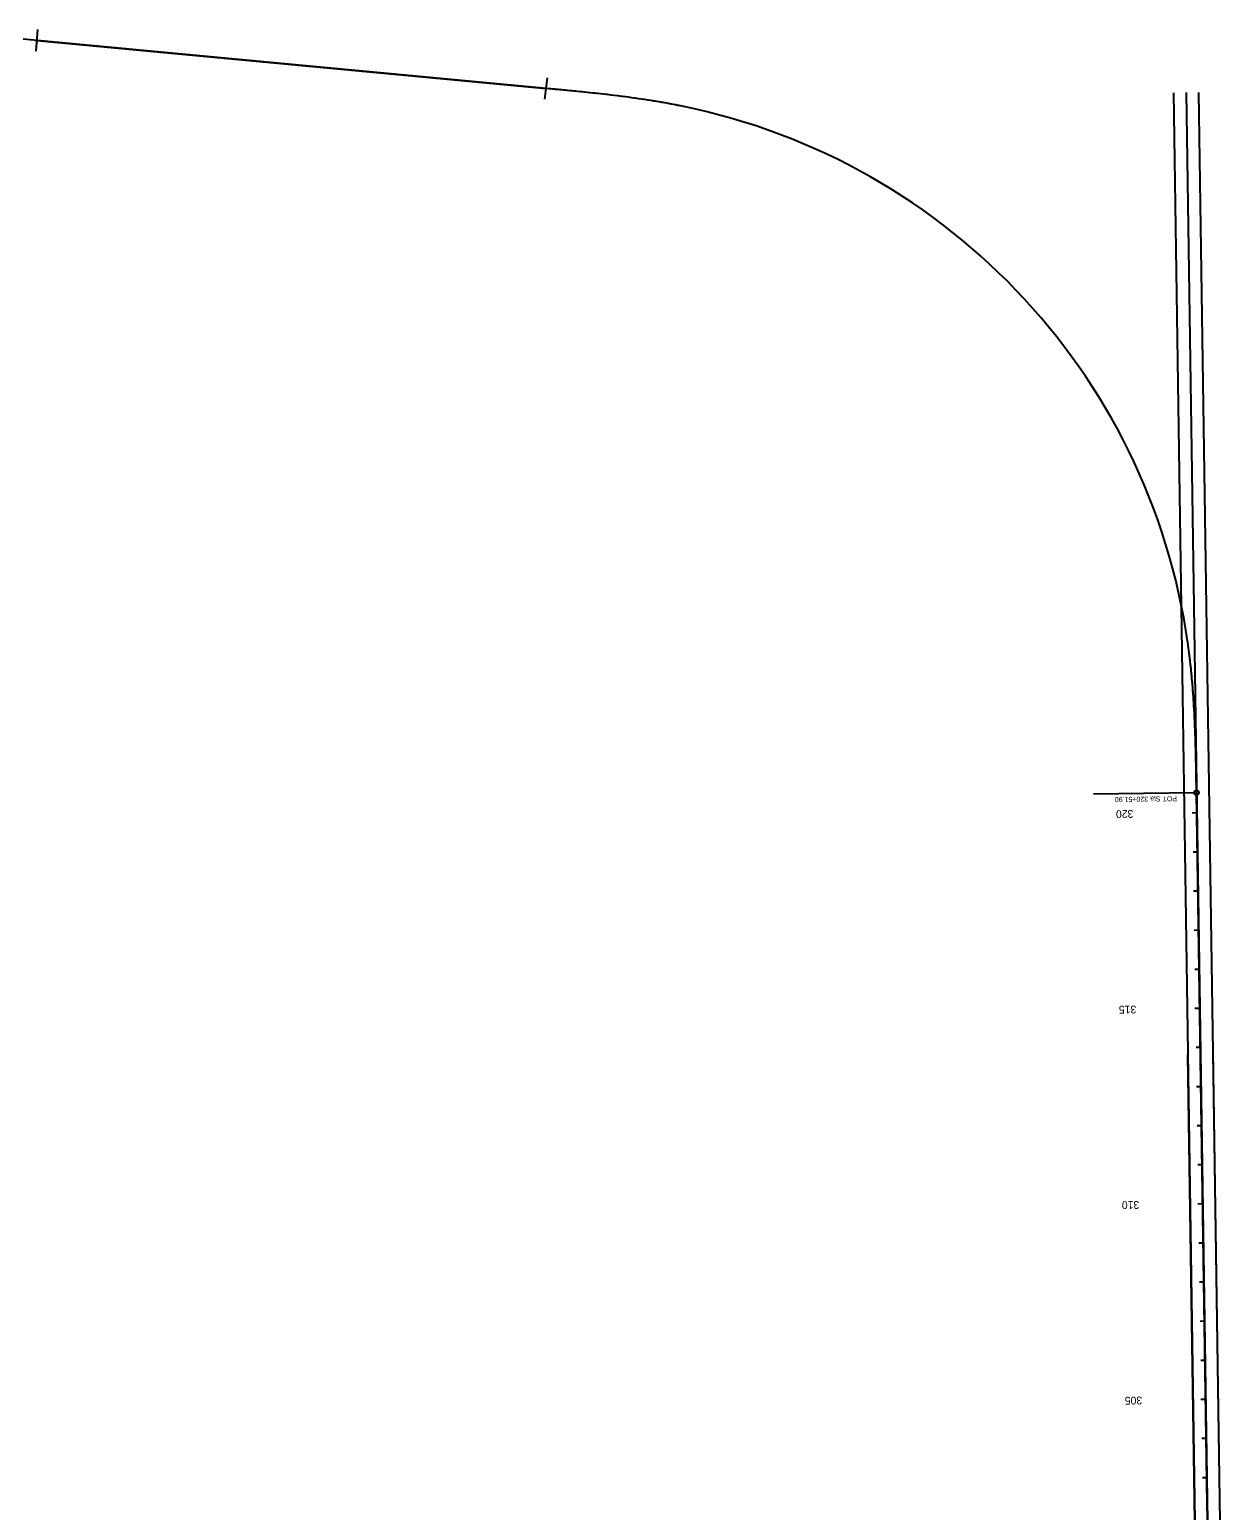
# Model space of a CAD drawing. Extents: x 5180909 to 5237144, y 3695282 to 3720102.
# Drawn here: x 5193765 to 5196834, y 3713664 to 3717451 of the extents above; entities that cross this region are included whole.
import ezdxf

# ---------------------------------------------------------------- set-up
doc = ezdxf.new("R2010")
doc.units = 0
for name, color, linetype in [('Alignment', 7, 'Continuous'), ('DisFieldPoint', 7, 'Continuous'), ('dsnEntranceCL', 7, 'Continuous'), ('dsnEntrancePaved', 7, 'Continuous'), ('dsnShadingGranular', 7, 'Continuous'), ('dsnSidewalkShadingRamp', 7, 'Continuous')]:
    doc.layers.add(name, color=color, linetype=linetype)

msp = doc.modelspace()

# ---------------------------------------------------------------- linework, layer by layer
at = {"layer": 'Alignment'}
for p, q in [((5195086.9, 3717300), (5193748.7, 3717426.1)), ((5196789.7, 3712837.6), (5196749.6, 3715500.4))]:
    msp.add_line(p, q, dxfattribs=at)
msp.add_arc((5195107.1, 3715650.6), 1637, 6.9864, 78.4885, dxfattribs=at)
for points in [[(5195433.7, 3717254.7), (5195424.2, 3717256.7), (5195405.1, 3717260.4), (5195366.8, 3717267.2), (5195318.8, 3717274.6), (5195261, 3717282.1), (5195203, 3717288.7), (5195154.6, 3717293.5), (5195115.9, 3717297.2), (5195096.5, 3717299), (5195086.9, 3717300)], [(5196749.6, 3715500.4), (5196749.5, 3715510.1), (5196749.2, 3715529.5), (5196748.6, 3715568.4), (5196747.5, 3715617), (5196745.6, 3715675.3), (5196742.7, 3715733.6), (5196739.1, 3715782.1), (5196735.3, 3715820.8), (5196733.1, 3715840.1), (5196731.9, 3715849.8)]]:
    msp.add_open_spline(points, degree=3, dxfattribs=at)
at = {"layer": 'DisFieldPoint'}
for p, q in [((5196769.8, 3712072.4), (5196691.7, 3717288.9)), ((5196801.8, 3712072.9), (5196723.7, 3717289.4)), ((5196833.8, 3712073.4), (5196755.7, 3717289.9))]:
    msp.add_line(p, q, dxfattribs=at)
at = {"layer": 'dsnEntranceCL'}
for p, q in [((5193783.3, 3717422.9), (5195086.2, 3717300)), ((5196777, 3713680.1), (5196749.7, 3715499.1)), ((5196777, 3713680.1), (5196749.7, 3715499.1))]:
    msp.add_line(p, q, dxfattribs=at)
msp.add_arc((5195107.1, 3715650.6), 1637, 6.9864, 78.4885, dxfattribs=at)
for points in [[(5195433.7, 3717254.7), (5195419.5, 3717257.6), (5195390.8, 3717263.1), (5195333.2, 3717272.6), (5195261, 3717282.4), (5195188.5, 3717290.2), (5195130.4, 3717295.8), (5195101.4, 3717298.6), (5195086.9, 3717300)], [(5196749.6, 3715500.4), (5196749.4, 3715515), (5196749, 3715544.1), (5196747.9, 3715602.5), (5196745.8, 3715675.3), (5196741.8, 3715748.2), (5196736.9, 3715806.3), (5196733.7, 3715835.3), (5196731.9, 3715849.8)]]:
    msp.add_open_spline(points, degree=3, dxfattribs=at)
at = {"layer": 'dsnEntrancePaved'}
msp.add_line((5196789.7, 3712837.6), (5196749.6, 3715500.4), dxfattribs=at)
at = {"layer": 'dsnShadingGranular'}
for p, q in [((5196822.2, 3712838.1), (5196792.1, 3714838.8)), ((5196757.7, 3712837.1), (5196727.7, 3714828.4))]:
    msp.add_line(p, q, dxfattribs=at)
at = {"layer": 'dsnSidewalkShadingRamp'}
for p, q in [((5193785.2, 3717450.5), (5193781.4, 3717395.2)), ((5195082.9, 3717272.6), (5195089.6, 3717327.4)), ((5196743.4, 3715499), (5196486.4, 3715495.1)), ((5196750.4, 3715447.2), (5196738.2, 3715447)), ((5196751.9, 3715347.2), (5196740.9, 3715347.1)), ((5196753.4, 3715247.2), (5196742.4, 3715247.1)), ((5196754.9, 3715147.2), (5196743.9, 3715147.1)), ((5196756.5, 3715047.3), (5196745.5, 3715047.1)), ((5196758, 3714947.3), (5196745.7, 3714947.1)), ((5196759.5, 3714847.3), (5196748.5, 3714847.1)), ((5196761, 3714747.3), (5196750, 3714747.1)), ((5196762.5, 3714647.3), (5196751.5, 3714647.1)), ((5196764, 3714547.3), (5196753, 3714547.1)), ((5196765.5, 3714447.3), (5196753.2, 3714447.1)), ((5196767, 3714347.3), (5196756, 3714347.2)), ((5196768.5, 3714247.3), (5196757.5, 3714247.2)), ((5196770, 3714147.4), (5196759, 3714147.2)), ((5196771.5, 3714047.4), (5196760.5, 3714047.2)), ((5196773, 3713947.4), (5196760.7, 3713947.2)), ((5196774.5, 3713847.4), (5196763.5, 3713847.2)), ((5196776, 3713747.4), (5196765, 3713747.2))]:
    msp.add_line(p, q, dxfattribs=at)
msp.add_circle((5196749.7, 3715499.1), 6.25, dxfattribs=at)

# ---------------------------------------------------------------- texts
for s, height, p in [('POT Sta 320+51.90', 13, (5196699.8, 3715490.3)), ('320', 20, (5196588.1, 3715454.8)), ('315', 20, (5196595.6, 3714954.8)), ('310', 20, (5196603.1, 3714454.9)), ('305', 20, (5196610.6, 3713954.9))]:
    msp.add_text(s, height=height, rotation=180.8614, dxfattribs=at).set_placement(p)

doc.saveas('drawing.dxf')
